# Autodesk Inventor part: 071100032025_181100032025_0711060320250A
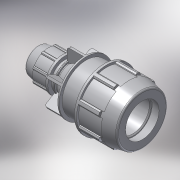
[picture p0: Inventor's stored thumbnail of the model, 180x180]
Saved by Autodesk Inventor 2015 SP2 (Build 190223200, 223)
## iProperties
Created: 2017-02
Part Number: 071100032025_181100032025_0711060320250A
Material: PVC-Piping
Description: PLASSON REDUCING COUPLER 32-25
Document SubType Name: Modeling
Designer: KIM
Mass: 92.6774 g
Surface Area: 199.44 cm^2
Volume: 66.1981 cm^3
Density: 1.4 g/cm^3
Appearance: Smooth - White
Author: KIM
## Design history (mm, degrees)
derived "07110.ipt"
feature "Solid1::07110.ipt"
tag "TaggingFeature1"
body "Solid1"
other parameters: "d2" = 32, "d4" = 11.08333, "d5" = 19, "d7" = 64, "d9" = 19, "d11" = 1.9, "d12" = 51.2, "d13" = 120 deg, "d14" = 48, "d15" = 12 deg, "d16" = 57.6, "d18" = 1.6, "d19" = 35 deg, "d20" = 17.5 deg, "d21" = 59.52, "d23" = 0, "d25" = 360 deg, "d27" = 1.28, "d42" = 29.26, "d46" = 0.96, "d51" = 133, "d52" = 19, "d53" = 12 deg, "d54" = 67, "d56" = 37.5, "d57" = 25, "d58" = 28.8, "d59" = 22.5, "d60" = 48.6, "d61" = 43.2, "d62" = 13.3, "d63" = 21.28, "d64" = 120 deg, "d65" = 54, "d68" = 9.5, "d74" = 50.22, "d75" = 35 deg, "d76" = 17.5 deg, "d78" = 0, "d80" = 360 deg, "d85" = 1.08, "d88" = 0.5, "d93" = 58, "d94" = 44.8, "d97" = 2.25, "d98" = 3.6, "d99" = 0, "d100" = 2.56, "d102" = 360 deg, "d104" = 2, "d106" = 0, "d107" = 3.6, "d108" = 0, "d109" = 3.6, "d110" = 0, "d_" = 32, "E_" = 64, "H_" = 133, "l_" = 67, "d_1" = 25, "E_1" = 54, "l_1" = 58, "d96" = 6.75
